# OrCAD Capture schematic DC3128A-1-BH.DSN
size Custom; note: 100MHz - 70 GHz RMS POWER DETECTOR
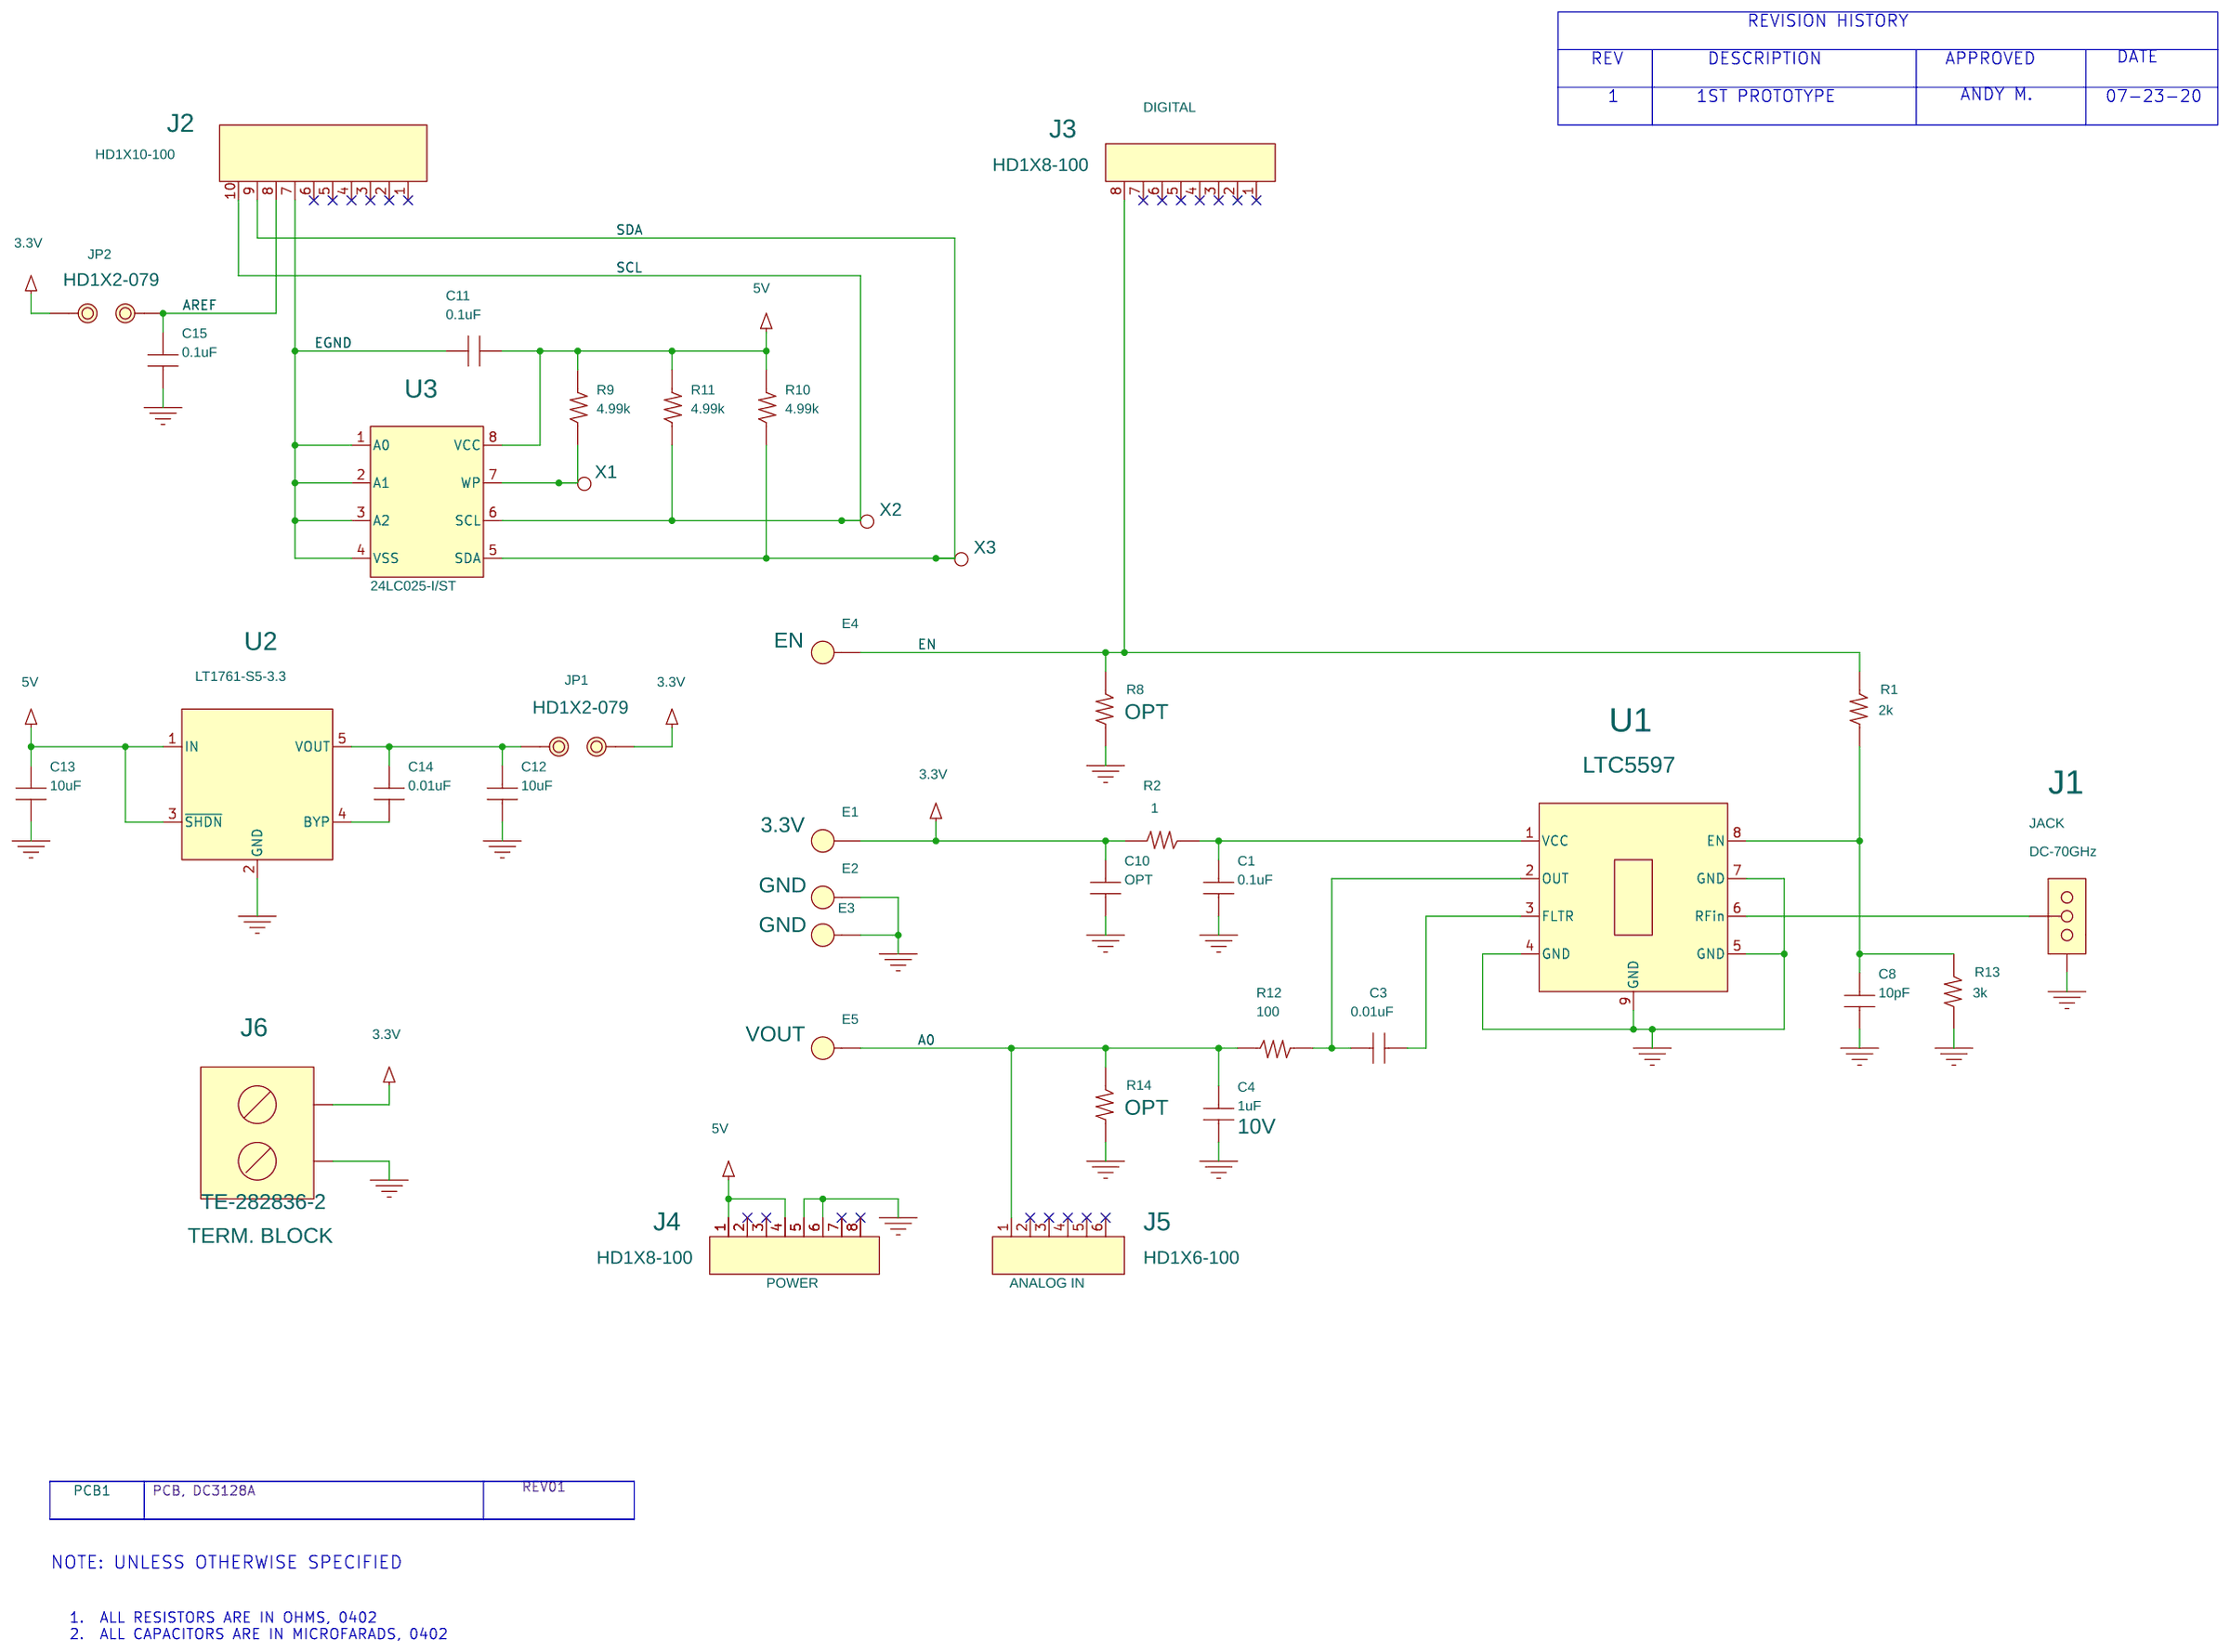
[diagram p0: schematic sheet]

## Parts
C1  0.1uF  [CC0402N]
C3  0.01uF  [CC0402N]
C4  1uF  [CC0402N]
C8  10pF  [CC0402N]
C10  OPT  [CC0402N]
C11  0.1uF  [CC0402N]
C12  10uF  [CC0402N]
C13  10uF  [CC0402N]
C14  0.01uF  [CC0402N]
C15  0.1uF  [CC0402N]
E1  TEST POINT  [MILLMAX2308]
E2  TEST POINT  [MILLMAX2308]
E3  TEST POINT  [MILLMAX2308]
E4  TEST POINT  [MILLMAX2308]
E5  TEST POINT  [MILLMAX2308]
J1  JACK  [SRI-25-146-1000-93]
J2  HDR  [HD1X10-100]
J3  HDR  [HD1X8-100]
J4  HDR  [HD1X8-100]
J5  HDR  [HD1X6-100]
J6  TERM. BLOCK  [TE-282836-2]
JP1  HDR  [HD1X2-079]
JP2  HDR  [HD1X2-079]
PCB1  PCB, DC3128A  [MECHANICAL_PART]
R1  2k  [CR0402N]
R2  1  [CR0402N]
R8  OPT  [CR0402N]
R9  4.99k  [CR0402N]
R10  4.99k  [CR0402N]
R11  4.99k  [CR0402N]
R12  100  [CR0402N]
R13  3k  [CR0402N]
R14  OPT  [CR0402N]
U1  LTC5597IDC  [LTC-DC-8-1957]
U2  LT1761-S5-3.3  [LTC-S5-5-1635]
U3  24LC025-I/ST  [MICROCHIP-TSSOP-8]
X1  E-SMT-060  [PAD060-SMT-T]
X2  E-SMT-060  [PAD060-SMT-T]
X3  E-SMT-060  [PAD060-SMT-T]

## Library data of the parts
C1 = CAP_ALT: CAP.,0.1uF,Si RF,11V,15%,0402,ULTRA-BROADBAND; 1: 40GHz; CLASS: DISCRETE; Dielectric Type: Si RF; Inventory Qty: 0; Manufacturer: MURATA; Manufacturer PN: 935152424610-T3N; PART_NUMBER: 150-1828; Package Size: 0402; Rated Voltage: 11V; Tolerance: 15%
C3 C14 = CAP_ALT: CAP.,0.01uF,X7R,16V,10%,0402; CLASS: DISCRETE; Dielectric Type: X7R; FPLIST: CC0402N,CC0402L,CC0402M; Inventory Qty: 18936; Manufacturer: MURATA; Manufacturer PN: GRM155R71C103KA01D; PART_NUMBER: 150-0158; Package Size: 0402; Rated Voltage: 16V; Tolerance: 10%
C4 = CAP_ALT: CAP.,1uF,X5R,10V,10%,0402; CLASS: DISCRETE; Dielectric Type: X5R; FPLIST: CC0402N,CC0402L,CC0402M; Inventory Qty: 90820; Manufacturer: MURATA; Manufacturer PN: GRM155R61A105KE15D; PART_NUMBER: 150-3493; Package Size: 0402; Rated Voltage: 10V; Tolerance: 10%
C8 = CAP_ALT: CAP.,10pF,NP0,50V,10%,0402; CLASS: DISCRETE; Dielectric Type: NP0; FPLIST: CC0402N,CC0402L,CC0402M; Inventory Qty: 30218; Manufacturer: AVX; Manufacturer PN: 04025A100KAT2A; PART_NUMBER: 150-3121; Package Size: 0402; Rated Voltage: 50V; Tolerance: 10%
C10 = CAP_ALT: CAP., OPTION, 0402; CLASS: DISCRETE; FPLIST: CC0402N,CC0402L,CC0402M; PART_NUMBER: 150-3148; Package Size: 0402; Package Type: SMD
C11 C15 = CAP_ALT: CAP.,0.1uF,X7R,16V,10%,0402; CLASS: DISCRETE; Dielectric Type: X7R; FPLIST: CC0402N,CC0402L,CC0402M; Inventory Qty: 59180; Manufacturer: AVX; Manufacturer PN: 0402YC104KAT2A; PART_NUMBER: 150-3065; Package Size: 0402; Package Type: SMD; Rated Voltage: 16V; Tolerance: 10%
C12 C13 = CAP_ALT: CAP.,10uF,X5R,6.3V,20%,0402; CLASS: DISCRETE; Dielectric Type: X5R; FPLIST: CC0402N, CC0402M,CC0402L; Inventory Qty: 27804; Manufacturer: MURATA; Manufacturer PN: GRJ155R60J106ME11D; PART_NUMBER: 150-2653; Package Size: 0402; Package Type: Surface Mount, MLCC; Rated Voltage: 6.3V; Temperature Coefficient: X5R; Tolerance: 20%
E1 = TEST_POINT_.156_MILL-MAX_2308: TEST POINT,TURRET,0.064" MTG. HOLE,PCB 0.062" THK; 1: 3.3V; CLASS: IO; Inventory Qty: 905744; Manufacturer: MILL-MAX; Manufacturer PN: 2308-2-00-80-00-00-07-0; PART_NUMBER: 260-0004
E2 E3 = TEST_POINT_.156_MILL-MAX_2308: TEST POINT,TURRET,0.064" MTG. HOLE,PCB 0.062" THK; 1: GND; CLASS: IO; Inventory Qty: 905744; Manufacturer: MILL-MAX; Manufacturer PN: 2308-2-00-80-00-00-07-0; PART_NUMBER: 260-0004
E4 = TEST_POINT_.156_MILL-MAX_2308: TEST POINT,TURRET,0.064" MTG. HOLE,PCB 0.062" THK; 1: EN; CLASS: IO; Inventory Qty: 905744; Manufacturer: MILL-MAX; Manufacturer PN: 2308-2-00-80-00-00-07-0; PART_NUMBER: 260-0004
E5 = TEST_POINT_.156_MILL-MAX_2308: TEST POINT,TURRET,0.064" MTG. HOLE,PCB 0.062" THK; 1: VOUT; CLASS: IO; Inventory Qty: 905744; Manufacturer: MILL-MAX; Manufacturer PN: 2308-2-00-80-00-00-07-0; PART_NUMBER: 260-0004
J1 = WINCHESTER-25-146-1000-93: CONN.,JACK,RCPT,FEMALE,1.85mm,END LAUNCH; CLASS: IO; Inventory Qty: 0; Manufacturer: SOUTHWEST MICROWAVE; Manufacturer PN: 1892-03A-6; PART_NUMBER: 250-0970; VALUE1: DC-70GHz
J2 = CON10: CONN.,HDR,MALE,1x10,2.54mm,VERT,ST,THT; CLASS: IO; Inventory Qty: 10828; Manufacturer: SAMTEC; Manufacturer PN: TSW-110-07-L-S; PART_NUMBER: 250-0606
J3 = CON8: CONN.,HDR,MALE,1x8,2.54mm,THT,STR; 1: DIGITAL; CLASS: IO; Inventory Qty: 0; Manufacturer: SAMTEC; Manufacturer PN: TSW-108-07-L-S; PART_NUMBER: 250-0784
J4 = CON8: CONN.,HDR,MALE,1x8,2.54mm,THT,STR; 1: POWER; CLASS: IO; Inventory Qty: 0; Manufacturer: SAMTEC; Manufacturer PN: TSW-108-07-L-S; PART_NUMBER: 250-0784
J5 = CON6: CONN.,HDR,MALE,1x6,2.54mm,VERT,ST,THT; 1: ANALOG IN; CLASS: IO; Inventory Qty: 11394; Manufacturer: SAMTEC; Manufacturer PN: TSW-106-07-L-S; PART_NUMBER: 250-0537
J6 = TERMINAL_BLOCK_WITH_SCREW: CONN.,TERM. BLOCK,RCPT,1x2,5mm,SIDE ENTRY, THT; CLASS: IO; Inventory Qty: 2778; Manufacturer: TE CONNECTIVITY; Manufacturer PN: 282836-2; PART_NUMBER: 250-0752
JP1 = HDR1X2_ALT1: CONN.,HDR,MALE,1x2,2mm,VERT,ST,THT,10u" Au; CLASS: IO; Inventory Qty: 10448; Manufacturer: SAMTEC; Manufacturer PN: TMM-102-02-L-S; PART_NUMBER: 250-0420
JP2 = HDR1X2_ALT1_1: CONN.,HDR,MALE,1x2,2mm,VERT,ST,THT,10u" Au; CLASS: IO; Inventory Qty: 10448; Manufacturer: SAMTEC; Manufacturer PN: TMM-102-02-L-S; PART_NUMBER: 250-0420
PCB1 = BLANK_PCB_PART: BOM Notes: REV01; CLASS: DISCRETE; Inventory Qty: 0; Manufacturer: ADI APPROVED SUPPLIER; Manufacturer PN: 600-DC3128A; PART_NUMBER: 600-DC3128A
R1 = RES_ALT: RES.,2k OHMS,1%,1/16W,0402,AEC-Q200; CLASS: DISCRETE; FPLIST: CR0402N,CR0402L,CR0402M; Inventory Qty: 34052; Manufacturer: VISHAY; Manufacturer PN: CRCW04022K00FKED; PART_NUMBER: 100-0018; Package Size: 0402; Rated Power: 1/16W; Temperature Coefficient: 100ppm/C; Tolerance: 1%
R2 = RES_ALT: RES.,1 OHM,1%,1/16W,0402,AEC-Q200; CLASS: DISCRETE; FPLIST: CR0402N,CR0402L,CR0402M; Inventory Qty: 34224; Manufacturer: VISHAY; Manufacturer PN: CRCW04021R00FKED; PART_NUMBER: 100-0241; Package Size: 0402; Rated Power: 1/16W; Temperature Coefficient: +/-100ppm; Tolerance: 1%
R8 R14 = RES_ALT: RES., OPTION, 0402; CLASS: DISCRETE; FPLIST: CR0402N,CR0402L,CR0402M; PART_NUMBER: 100-0357; Package Size: 0402
R9-R11 = RES_ALT: RES.,4.99k OHMS,1%,1/16W,0402; CLASS: DISCRETE; FPLIST: CR0402N,CR0402L,CR0402M; Inventory Qty: 83411; Manufacturer: NIC; Manufacturer PN: NRC04F4991TRF; PART_NUMBER: 100-2625; Package Size: 0402; Rated Power: 1/16W; Temperature Coefficient: 100ppm/C; Tolerance: 1%
R12 = RES_ALT: RES.,100 OHMS,1%,1/16W,0402; CLASS: DISCRETE; FPLIST: CR0402N,CR0402L,CR0402M; Inventory Qty: 49272; Manufacturer: NIC; Manufacturer PN: NRC04F1000TRF; PART_NUMBER: 100-2626; Package Size: 0402; Rated Power: 1/16W; Temperature Coefficient: 100ppm/C; Tolerance: 1%
R13 = RES_ALT: RES.,3k OHMS,5%,1/16W,0402,AEC-Q200; CLASS: DISCRETE; FPLIST: CR0402N,CR0402L,CR0402M; Inventory Qty: 19846; Manufacturer: NIC; Manufacturer PN: NRC04J302TRF; PART_NUMBER: 100-2081; Package Size: 0402; Rated Power: 1/16W; Temperature Coefficient: +/-200PPM; Tolerance: 5%
U1 = LTC5597IDC-DFN8DC: IC,100MHz-70GHz RMS PWR DETECTOR,DFN8DC; CLASS: IC; Inventory Qty: 17; Manufacturer: ANALOG DEVICES; Manufacturer PN: LTC5597IDC#PBF; PART_NUMBER: LTC5597IDC#PBF; Package Type: DFN8DC; VALUE1: LTC5597
U2 = LT1761-S5-X: IC,Low Noise, LDO uPower Reg.,TSOT23-5; CLASS: IC; Inventory Qty: 175; Manufacturer: LINEAR TECH.; Manufacturer PN: LT1761ES5-3.3#PBF; PART_NUMBER: LT1761ES5-3.3#PBF; Package Type: TSOT23-5
U3 = 24LC025-I_ST_TSSOP-8: IC, MEMORY,EEPROM,2Kb (256x8),TSSOP-8,400kHz; CLASS: IC; Inventory Qty: 16131; Manufacturer: Microchip; PART_NUMBER: 380-0087; Package Size: TSSOP-8; Package Type: TSSOP-8
X1-X3 = E-SMT-060_0

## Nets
3.3V: C10.1 E1.1(A) J6.1 JP1.1 JP2.2 R2.2
5V: C11.2 C13.1 J4.1 J4.4 R9.2 R10.2 R11.2 U2.1(IN) U2.3(~{SHDN}) U3.8(VCC)
GND: C1.1 C4.2 C8.2 C10.2 C12.2 C13.2 C15.2 E2.1(A) E3.1(A) J1.2(GND) J1.3(GND) J4.5 J4.6 J6.2 R8.2 R13.2 R14.2 U1.4(GND) U1.5(GND) U1.7(GND) U1.9(GND) U2.2(GND)
A0: C4.1 E5.1(A) J5.1 R12.1 R14.1
AREF: C15.1 J2.8 JP2.1
EGND: C11.1 J2.7 U3.1(A0) U3.2(A1) U3.3(A2) U3.4(VSS)
EN: E4.1(A) J3.8 R1.1 R8.1
SCL: J2.10 R11.1 U3.6(SCL) X2.1
SDA: J2.9 R10.1 U3.5(SDA) X3.1
N16954081: J1.1(CENTER) U1.6(RFin)
N16954948: C8.1 R1.2 R13.1 U1.8(EN)
N16959227: C1.2 R2.1 U1.1(VCC)
N16965086: C3.1 U1.3(FLTR)
N17008263: R9.1 U3.7(WP) X1.1
N17011670: C12.1 C14.2 JP1.2 U2.5(VOUT)
N17012093: C14.1 U2.4(BYP)
N17013963: C3.2 R12.2 U1.2(OUT)

Not connected (* = marked no-connect by the designer): J2 1* 2* 3* 4* 5* 6*; J3 1* 2* 3* 4* 5* 6* 7*; J4 2* 3* 7* 8*; J5 2* 3* 4* 5* 6*

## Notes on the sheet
- REVISION HISTORY
- REV
- DESCRIPTION
- APPROVED
- DATE
- 1
- 1ST PROTOTYPE
- ANDY M.
- 07-23-20
- NOTE: UNLESS OTHERWISE SPECIFIED
- 1.  ALL RESISTORS ARE IN OHMS, 0402
  2.  ALL CAPACITORS ARE IN MICROFARADS, 0402
